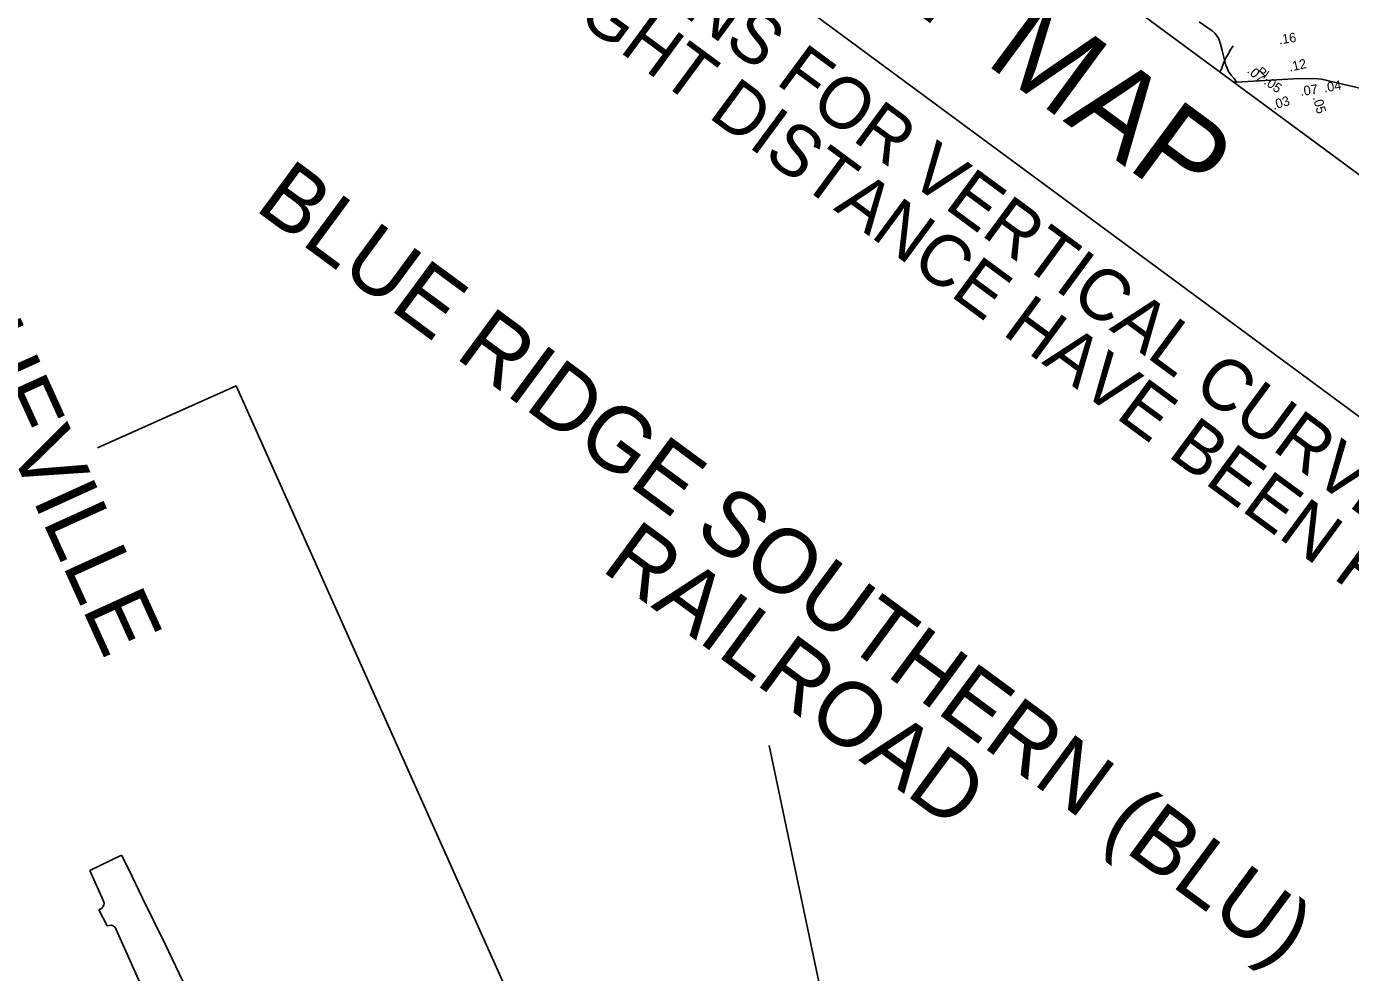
# Model space of a CAD drawing. Extents: x 945666 to 965748, y 644452 to 663300.
# Drawn here: x 951483 to 953745, y 656097 to 657713 of the extents above; entities that cross this region are included whole.
import ezdxf

# ---------------------------------------------------------------- set-up
doc = ezdxf.new("R2010")
doc.units = 0
for name, color, linetype in [('Exist Hydrographic Misc Water Feature', 7, 'Continuous'), ('Exist Road Secondary Mileage Tenths English Label', 7, 'Continuous'), ('Exist Road Secondary Type 51 Attributed', 7, 'Continuous'), ('Exist Road Secondary Type 51 Label', 7, 'Continuous'), ('Old_Level_1', 7, 'Continuous'), ('Old_Level_23', 7, 'Continuous'), ('Old_Level_38', 7, 'Continuous'), ('Prop Shade Light', 7, 'Continuous'), ('Sheet Data Field CELL', 7, 'Continuous'), ('Sheet Plan Layout CELL', 7, 'Continuous'), ('Sheet Sticker Preliminary CELL', 7, 'Continuous')]:
    doc.layers.add(name, color=color, linetype=linetype)

msp = doc.modelspace()

# ---------------------------------------------------------------- linework, layer by layer
at = {"layer": 'Exist Hydrographic Misc Water Feature'}
msp.add_lwpolyline([(953544.6, 657679.6), (953540.7, 657674), (953536, 657665.6), (953531.6, 657657.8), (953527.8, 657649.4), (953525.9, 657643.9), (953524.6, 657639.9), (953521.7, 657635.5)], dxfattribs=at)
at = {"layer": 'Exist Road Secondary Type 51 Attributed'}
for points in [[(953486.2, 657720.5), (953499.4, 657711.5), (953508.4, 657705.6)], [(953508.4, 657705.6), (953513.8, 657700.5), (953516.5, 657696.7), (953519.9, 657691.5), (953522.7, 657682.5)], [(953522.7, 657682.5), (953525.8, 657671.6), (953532.1, 657646.9), (953534.2, 657641.3), (953536.5, 657635.7), (953540.9, 657629.4), (953546.4, 657623.7), (953550.1, 657617.9)], [(953545.8, 657617.6), (953550.1, 657617.9)], [(953550.1, 657617.9), (953647.7, 657623.1), (953683.5, 657623.9), (953695.4, 657622.6), (953702.8, 657621.1), (953709.6, 657619.6), (953773.6, 657604.5), (953793.9, 657600), (953840.1, 657589.8)]]:
    msp.add_lwpolyline(points, dxfattribs=at)
at = {"layer": 'Old_Level_1'}
for points in [[(953667.4, 661172.9), (956829.7, 658840.6), (955088.6, 656479.8), (951926.2, 658812.1)], [(951728.9, 658544.5), (954891.3, 656212.2), (955088.6, 656479.8), (951926.2, 658812.1)]]:
    msp.add_lwpolyline(points, close=True, dxfattribs=at)
at = {"layer": 'Old_Level_23'}
msp.add_line((952752.1, 656484.8), (952987.9, 655359.8), dxfattribs=at)
at = {"layer": 'Prop Shade Light'}
for p, q in [((951645.7, 656297.5), (951591.5, 656271.4)), ((951591.5, 656271.4), (951614.9, 656219.1)), ((951611.1, 656206.6), (951606.9, 656203.9)), ((951606.9, 656203.9), (951620.7, 656176.6)), ((951620.7, 656176.6), (951624.7, 656177.5)), ((951636, 656171.9), (951682, 656068.9))]:
    msp.add_line(p, q, dxfattribs=at)
msp.add_lwpolyline([(951781.9, 656018), (951766.2, 656050.3), (951744.2, 656095.3), (951720.1, 656145.4), (951681.2, 656224.3), (951657.7, 656273), (951645.7, 656297.5)], dxfattribs=at)
for centre, start, end in [((951605.7, 656215.1), 302.7103, 24.0909), ((951626.9, 656167.8), 24.0909, 102.7451)]:
    msp.add_arc(centre, 10, start, end, dxfattribs=at)
at = {"layer": 'Sheet Plan Layout CELL'}
for p, q in [((951841.4, 657099.2), (951604.2, 656993)), ((952375.8, 655905.5), (951841.4, 657099.2))]:
    msp.add_line(p, q, dxfattribs=at)

# ---------------------------------------------------------------- texts
at = {"layer": 'Exist Road Secondary Mileage Tenths English Label'}
for s, rotation, p in [('.07', 319.438, (953567.2, 657635.2)), ('.05', 324.731, (953595.7, 657615.6)), ('.03', 16.633, (953613.7, 657570.4))]:
    msp.add_text(s, height=16.24, rotation=rotation, dxfattribs=at).set_placement(p)
at = {"layer": 'Exist Road Secondary Type 51 Label'}
msp.add_text('Pl.', height=15, rotation=323.5908, dxfattribs=at).set_placement((953583.9, 657633.1))
at = {"layer": 'Old_Level_23'}
for s, rotation, p in [('TO ASHEVILLE', 294.4374, (951185.1, 657582.4)), ('BLUE RIDGE SOUTHERN (BLU) ', 323.5908, (951870.9, 657401)), ('RAILROAD', 323.5908, (952462.9, 656785.1))]:
    msp.add_text(s, height=110, rotation=rotation, dxfattribs=at).set_placement(p)
at = {"layer": 'Old_Level_38'}
msp.add_text('VICINITY MAP', height=150, rotation=323.5908, dxfattribs=at).set_placement((952391.6, 658186.9))
at = {"layer": 'Sheet Data Field CELL'}
for s, p in [('1. DESIGN EXCEPTIONS FOR VERTICAL CURVE K VALUE', (951636, 658446)), (' AND STOPPING SIGHT DISTANCE HAVE BEEN REQUESTED', (951567.9, 658353.7))]:
    msp.add_text(s, height=87.501, rotation=323.5908, dxfattribs=at).set_placement(p)
at = {"layer": 'Sheet Sticker Preliminary CELL'}
for s, rotation, p in [('.16', 8.1467, (953623.3, 657682.2)), ('.12', 12.1829, (953641.4, 657635.6)), ('.04', 10.1063, (953700.5, 657599.9)), ('.07', 7.6395, (953660, 657594)), ('.05', 285.3868, (953680.3, 657591.5))]:
    msp.add_text(s, height=16.24, rotation=rotation, dxfattribs=at).set_placement(p)

doc.saveas('drawing.dxf')
